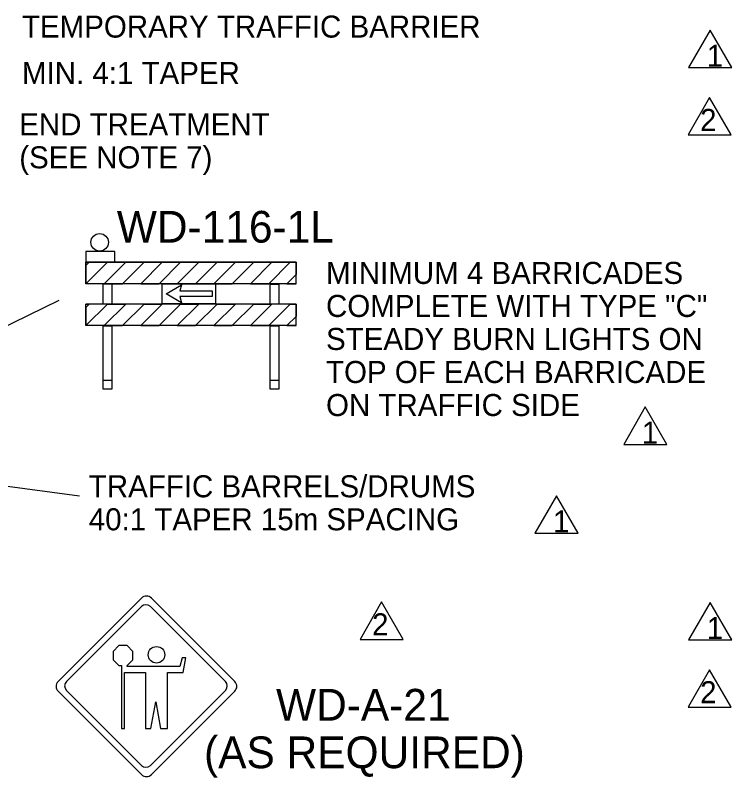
# Model space of a CAD drawing. Extents: x 2171 to 2395, y 134 to 413.
# Drawn here: x 2238.8 to 2286, y 275.8 to 326 of the extents above; entities that cross this region are included whole.
import ezdxf

# ---------------------------------------------------------------- set-up
doc = ezdxf.new("R2010")
doc.units = 0
for name, color, linetype in [('Level 1', 7, 'Continuous'), ('Level 10', 7, 'Continuous'), ('Level 44', 7, 'Continuous'), ('Level 5', 7, 'Continuous'), ('Level 60', 7, 'Continuous')]:
    doc.layers.add(name, color=color, linetype=linetype)

# ---------------------------------------------------------------- blocks, each defined once
blk = doc.blocks.new('REV1')
at = {"layer": 'Level 1'}
blk.add_lwpolyline([(0.114, 1.689), (-1.305, -0.781), (1.533, -0.781)], close=True, dxfattribs=at)
blk.add_text('1', height=1.448, rotation=360, dxfattribs=at).set_placement((-0.113, -0.724))

msp = doc.modelspace()

# ---------------------------------------------------------------- linework, layer by layer
at = {"layer": 'Level 1'}
for p, q in [((2245.642, 284.454), (2245.258, 284.07)), ((2246.184, 284.454), (2245.642, 284.454)), ((2246.568, 284.07), (2246.184, 284.454)), ((2245.258, 284.07), (2245.258, 283.528)), ((2246.568, 283.528), (2246.568, 284.07)), ((2245.258, 283.528), (2245.642, 283.144)), ((2246.184, 283.144), (2246.568, 283.528)), ((2249.8, 283.657), (2249.661, 283.074)), ((2250.044, 283.657), (2249.8, 283.657)), ((2249.885, 282.683), (2250.044, 283.657)), ((2245.642, 283.144), (2245.816, 283.144)), ((2245.816, 283.144), (2245.816, 278.991)), ((2246.184, 283.074), (2246.184, 283.144)), ((2249.661, 283.074), (2246.184, 283.074)), ((2246.006, 278.991), (2246.006, 282.683)), ((2246.006, 282.683), (2247.388, 282.683)), ((2247.388, 282.683), (2247.388, 278.991)), ((2248.838, 278.991), (2248.838, 282.683)), ((2248.838, 282.683), (2249.885, 282.683)), ((2247.755, 278.991), (2248.083, 280.76)), ((2248.083, 280.76), (2248.391, 278.991)), ((2245.816, 278.991), (2246.006, 278.991)), ((2247.388, 278.991), (2247.755, 278.991)), ((2248.391, 278.991), (2248.838, 278.991))]:
    msp.add_line(p, q, dxfattribs=at)
msp.add_circle((2248.118, 283.852), 0.544, dxfattribs=at)
at = {"layer": 'Level 10'}
msp.add_line((2243.047, 294.299), (2231.344, 295.868), dxfattribs=at)
msp.add_lwpolyline([(2243.471, 309.717), (2245.377, 309.717), (2245.377, 310.409), (2243.471, 310.409)], close=True, dxfattribs=at)
msp.add_circle((2244.378, 311.025), 0.576, dxfattribs=at)
at = {"layer": 'Level 44'}
for p, q in [((2247.134, 287.583), (2241.64, 282.097)), ((2253.268, 282.097), (2247.783, 287.583)), ((2242.19, 282.093), (2247.134, 287.03)), ((2247.718, 287.03), (2252.656, 282.093)), ((2241.64, 281.446), (2247.134, 275.955)), ((2241.645, 281.446), (2241.64, 281.446)), ((2247.134, 276.566), (2242.19, 281.506)), ((2252.656, 281.506), (2247.718, 276.566)), ((2247.783, 275.955), (2253.268, 281.446))]:
    msp.add_line(p, q, dxfattribs=at)
for centre, radius, start, end in [((2247.457, 287.259), 0.459, 45, 135), ((2247.425, 286.738), 0.413, 45, 135), ((2241.969, 281.771), 0.459, 135, 225), ((2242.485, 281.799), 0.413, 135, 225), ((2252.364, 281.799), 0.413, 315, 45), ((2252.946, 281.771), 0.459, 315, 45), ((2247.425, 276.859), 0.413, 225, 315), ((2247.457, 276.283), 0.459, 225, 315)]:
    msp.add_arc(centre, radius, start, end, dxfattribs=at)
at = {"layer": 'Level 5'}
for p, q in [((2257.313, 309.717), (2243.471, 309.717)), ((2243.471, 308.298), (2243.471, 309.717)), ((2243.471, 309.717), (2257.313, 309.717)), ((2245.741, 309.717), (2246.307, 309.717)), ((2257.313, 308.298), (2257.313, 309.717)), ((2257.313, 308.298), (2243.471, 308.298)), ((2244.606, 308.271), (2244.606, 308.298)), ((2248.524, 308.284), (2252.013, 308.284)), ((2248.524, 308.284), (2252.013, 308.284)), ((2255.612, 308.271), (2255.612, 308.298)), ((2241.683, 307.198), (2231.177, 302.067)), ((2243.471, 305.534), (2243.471, 306.952)), ((2257.313, 306.952), (2243.471, 306.952)), ((2252.013, 306.98), (2248.524, 306.98)), ((2252.013, 306.98), (2248.524, 306.98)), ((2256.179, 306.952), (2255.895, 306.952)), ((2257.313, 305.534), (2257.313, 306.952)), ((2257.313, 305.534), (2243.471, 305.534)), ((2245.173, 301.917), (2244.606, 301.917)), ((2256.179, 301.917), (2255.612, 301.917))]:
    msp.add_line(p, q, dxfattribs=at)
for points in [[(2243.471, 308.298), (2244.89, 309.717), (2243.687, 309.717), (2243.471, 309.502), (2243.471, 308.298)], [(2245.878, 308.298), (2247.297, 309.717), (2246.093, 309.717), (2244.675, 308.298), (2245.878, 308.298)], [(2248.285, 308.298), (2249.704, 309.717), (2248.5, 309.717), (2247.082, 308.298), (2248.285, 308.298)], [(2250.692, 308.298), (2252.11, 309.717), (2250.907, 309.717), (2249.489, 308.298), (2250.692, 308.298)], [(2254.517, 309.717), (2253.314, 309.717), (2251.895, 308.298), (2253.099, 308.298), (2254.517, 309.717)], [(2256.924, 309.717), (2255.721, 309.717), (2254.303, 308.298), (2255.506, 308.298), (2256.924, 309.717)], [(2257.313, 308.904), (2256.709, 308.298), (2257.313, 308.298), (2257.313, 308.904)], [(2243.471, 305.534), (2244.89, 306.952), (2243.687, 306.952), (2243.471, 306.737), (2243.471, 305.534)], [(2245.878, 305.534), (2247.297, 306.952), (2246.093, 306.952), (2244.675, 305.534), (2245.878, 305.534)], [(2248.285, 305.534), (2249.704, 306.952), (2248.5, 306.952), (2247.082, 305.534), (2248.285, 305.534)], [(2250.692, 305.534), (2252.11, 306.952), (2250.907, 306.952), (2249.489, 305.534), (2250.692, 305.534)], [(2254.517, 306.952), (2253.314, 306.952), (2251.895, 305.534), (2253.099, 305.534), (2254.517, 306.952)], [(2256.924, 306.952), (2255.721, 306.952), (2254.303, 305.534), (2255.506, 305.534), (2256.924, 306.952)], [(2257.313, 306.138), (2256.709, 305.534), (2257.313, 305.534), (2257.313, 306.138)]]:
    msp.add_lwpolyline(points, dxfattribs=at)
for points in [[(2244.89, 309.717), (2246.093, 309.717), (2244.675, 308.298), (2243.471, 308.298)], [(2243.687, 309.717), (2243.471, 309.717), (2243.471, 309.502)], [(2247.297, 309.717), (2248.5, 309.717), (2247.082, 308.298), (2245.878, 308.298)], [(2249.704, 309.717), (2250.907, 309.717), (2249.489, 308.298), (2248.285, 308.298)], [(2252.11, 309.717), (2253.314, 309.717), (2251.895, 308.298), (2250.692, 308.298)], [(2254.517, 309.717), (2255.721, 309.717), (2254.303, 308.298), (2253.099, 308.298)], [(2256.924, 309.717), (2257.313, 309.717), (2257.313, 308.904), (2256.709, 308.298), (2255.506, 308.298)], [(2244.606, 308.271), (2245.173, 308.298), (2245.173, 306.952), (2244.606, 306.952)], [(2252.013, 308.284), (2252.013, 306.952), (2248.5, 306.952), (2248.5, 308.284)], [(2251.786, 307.819), (2251.786, 307.445), (2249.659, 307.445), (2249.772, 307.047), (2248.752, 307.632), (2249.772, 308.216), (2249.659, 307.819)], [(2255.612, 308.271), (2256.179, 308.271), (2256.179, 306.952), (2255.612, 306.952)], [(2243.471, 306.952), (2243.687, 306.952), (2243.471, 306.737)], [(2244.89, 306.952), (2246.093, 306.952), (2244.675, 305.534), (2243.471, 305.534)], [(2247.297, 306.952), (2248.5, 306.952), (2247.082, 305.534), (2245.878, 305.534)], [(2249.704, 306.952), (2250.907, 306.952), (2249.489, 305.534), (2248.285, 305.534)], [(2252.11, 306.952), (2253.314, 306.952), (2251.895, 305.534), (2250.692, 305.534)], [(2254.517, 306.952), (2255.721, 306.952), (2254.303, 305.534), (2253.099, 305.534)], [(2256.924, 306.952), (2257.313, 306.952), (2257.313, 306.138), (2256.709, 305.534), (2255.506, 305.534)], [(2244.606, 305.519), (2245.173, 305.519), (2245.173, 301.349), (2244.606, 301.349)], [(2255.612, 305.519), (2256.179, 305.519), (2256.179, 301.349), (2255.612, 301.349)]]:
    msp.add_lwpolyline(points, close=True, dxfattribs=at)
at = {"layer": 'Level 60'}
for points in [[(2284.533, 320.564), (2283.14, 318.139)], [(2285.927, 318.139), (2284.533, 320.564)], [(2283.14, 318.139), (2283.114, 318.094), (2285.953, 318.094), (2285.927, 318.139)], [(2262.94, 287.335), (2261.547, 284.91)], [(2264.334, 284.91), (2262.94, 287.335)], [(2261.547, 284.91), (2261.521, 284.865), (2264.36, 284.865), (2264.334, 284.91)], [(2284.533, 282.865), (2283.14, 280.44)], [(2285.927, 280.44), (2284.533, 282.865)], [(2283.14, 280.44), (2283.114, 280.395), (2285.953, 280.395), (2285.927, 280.44)]]:
    msp.add_lwpolyline(points, dxfattribs=at)

# ---------------------------------------------------------------- block references
at = {"layer": 'Level 1'}
for p in [(2284.453, 323.315), (2280.177, 298.488), (2274.333, 292.64), (2284.453, 285.615)]:
    msp.add_blockref('REV1', p, dxfattribs=at)

# ---------------------------------------------------------------- texts
at = {"layer": 'Level 10'}
for s, height, p in [('TEMPORARY TRAFFIC BARRIER', 1.451, (2239.264, 324.51)), ('MIN. 4:1 TAPER', 1.451, (2239.264, 321.454)), ('END TREATMENT', 1.45, (2239.086, 318.068)), ('(SEE NOTE 7)', 1.45, (2239.086, 315.898)), ('WD-116-1L', 2.09, (2245.506, 311.004)), ('MINIMUM 4 BARRICADES', 1.4514, (2259.279, 308.283)), ('COMPLETE WITH TYPE "C" ', 1.4514, (2259.279, 306.107)), ('STEADY BURN LIGHTS ON ', 1.4514, (2259.279, 303.931)), ('TOP OF EACH BARRICADE ', 1.4514, (2259.279, 301.755)), ('ON TRAFFIC SIDE', 1.4514, (2259.279, 299.579)), ('TRAFFIC BARRELS/DRUMS ', 1.4514, (2243.662, 294.227)), ('40:1 TAPER 15m SPACING', 1.4514, (2243.662, 292.051)), ('WD-A-21', 2.09, (2255.987, 279.514)), ('(AS REQUIRED)', 2.09001, (2251.247, 276.38))]:
    msp.add_text(s, height=height, dxfattribs=at).set_placement(p)
at = {"layer": 'Level 60'}
for p in [(2283.906, 318.363), (2262.313, 285.134), (2283.906, 280.664)]:
    msp.add_text('2', height=1.448, rotation=360, dxfattribs=at).set_placement(p)

doc.saveas('drawing.dxf')
